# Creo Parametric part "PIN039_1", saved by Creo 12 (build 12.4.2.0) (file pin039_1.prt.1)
Units: Custom; MM, KILOGRAM, SECS

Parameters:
  PTC_WM_ITERATION = "0"
  PTC_WM_VERSION = "-.0"
  PTC_WM_LIFECYCLE_STATE = "In Work"
  PTC_WM_LIFECYCLE = "MO_CADDocument"
  PTC_WM_CREATED_BY = "Maximilian Roepper (Z0017RMS: MO)"
  PTC_WM_CREATED_ON = "18-Sep-26 11:36:42 AM"
  PTC_WM_MODIFIED_BY = "Maximilian Roepper (Z0017RMS: MO)"
  PTC_WM_MODIFIED_ON = "18-Sep-26 11:36:46 AM"
  PDMLINKNUMBER = "PDM000071454759"
  PTC_WM_NAME = "pin039_1.prt"
  PTC_WM_NUMBER = "PDM000071454759"

Other parameters: WEIGHT, WEIGHT_FACTOR, WEIGHT_ADD, _MASS_TEMP, _DIFF_TEMP, MC_ERRORS, SUPPLIER

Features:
  1. coordinate system
  2. datum plane "PRT_YZ"
  3. datum plane "PRT_XY"
  4. datum plane "PRT_XZ"
  5. coordinate system
  6. datum axis
  7. datum axis
  8. datum axis
  9. coordinate system
  10. imported feature

Other named items: PRT, SIEMENS_MO, DRW_VIEW_ORG, PRT_X, PRT_Y, PRT_Z, CS0, ROUGH_GROB

Layers: 00_STD_CSYS-KSYS, 01_STD_PLANES-EBENEN, 02_STD_AXES-ACHSEN, 03_STD_CSYS-KSYS, 24_IMPORT_FEAT-IMPORT_KE

Surfaces: 10 plane, 4 cylinder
